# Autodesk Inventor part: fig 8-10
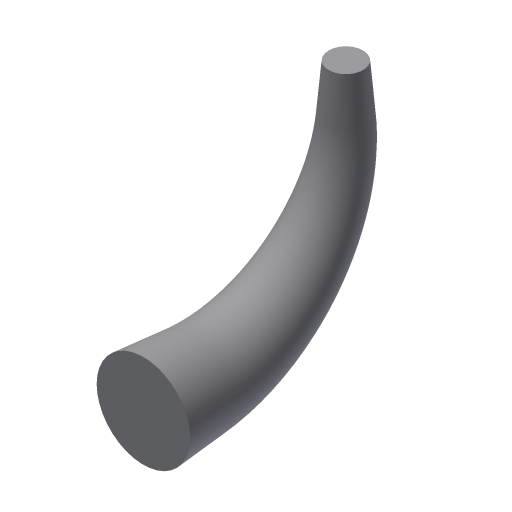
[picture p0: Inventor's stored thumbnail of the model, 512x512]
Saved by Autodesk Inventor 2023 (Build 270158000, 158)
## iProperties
Created: 2001-12
Part Number: fig 8-10
Document SubType Name: Modeling
Designer: CADSoft
Density: 1 g/cm^3
Material: Generic
Appearance: Default
Control State: 0
Master: False
Checked Out: False
Shininess: 77.0
Length Units: 11269
Angle Units: 11279
Time Units: 11290
Mass Units: 11283
Length Display Precision: 3
Angle Display Precision: 2
Density: 0.0
Volumn: 0.0
Area: 0.0
PropertySet Name: Model Information
Author: CADSoft
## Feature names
1. Sweep7
## Parameters: d4 = 15 mm, d5 = 15 mm, d13 = -5 deg, d14 = 0
